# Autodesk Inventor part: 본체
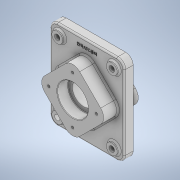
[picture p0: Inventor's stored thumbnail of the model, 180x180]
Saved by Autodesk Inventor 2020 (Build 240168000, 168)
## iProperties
Created: 2021-07
Part Number: 본체
Material: 일반
Document SubType Name: Modeling
Designer: Owner
Density: 1 g/cm^3
Appearance: 기본값
Mass: 807.977 g
Surface Area: 961.758 cm^2
Volume: 807.977 cm^3
Author: Owner
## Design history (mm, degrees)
sketch "스케치1"
  geometry: L1 (-75, -90)-(75, -90); L2 (75, -90)-(75, 90); L3 (75, 90)-(-75, 90); L4 (-75, 90)-(-75, -90); L5 (-75, -90)-(75, 90); L6 (75, -90)-(-75, 90); 1 further point
  constraints: 12 end point, 2 midpoint, 2 parallel, 1 horizontal, 1 perpendicular
  dimensions: "d0" = 150 distance of L3.end L2.end; "d1" = 180 distance of L2.end L1.end
extrude "돌출1" new body sketch "스케치1" stored distance "d2" = 18; taper "d3" = 0 deg
sketch "스케치2"
  geometry: L1 (-70.711, 0)-(0, 70.711); L2 (0, 70.711)-(70.711, 0); L3 (70.711, 0)-(0, -70.711); L4 (0, -70.711)-(-70.711, 0); L5 (-70.711, 0)-(70.711, 0); L6 (0, 70.711)-(0, -70.711); 2 further points
  constraints: 12 end point, 2 horizontal alignment, 2 midpoint, 2 parallel, 2 vertical alignment, 1 perpendicular
  dimensions: "d4" = 100 distance of L1.end L2.end; "d5" = 100 distance of L3.end L1.start (derived)
extrude "돌출2" join sketch "스케치2" distance "d6" = 29; taper "d7" = 0 deg
sketch "스케치3"
  geometry: L1 (-70.711, 0)-(0, 70.711); L2 (0, 70.711)-(70.711, 0); L3 (70.711, 0)-(0, -70.711); L4 (0, -70.711)-(-70.711, 0); L5 (-70.711, 0)-(70.711, 0); L6 (0, 70.711)-(0, -70.711); 2 further points
  constraints: 12 end point, 2 horizontal alignment, 2 midpoint, 2 parallel, 2 vertical alignment, 1 perpendicular
  dimensions: "d8" = 100 distance of L1.end L2.end; "d9" = 100 distance of L3.end L1.start (derived)
extrude "돌출3" join sketch "스케치3" distance "d10" = 23; taper "d11" = 0 deg
sketch "스케치5"
  geometry: C1 r 31 at (0, 0); 1 further point
  constraints: 1 centre point, 1 coincident
  dimensions: "d15" = 62 diameter of C1
extrude "돌출5" cut sketch "스케치5" distance "d16" = 22; taper "d17" = 0 deg
sketch "스케치6"
  geometry: C1 r 31 at (0, 0); 1 further point
  constraints: 1 centre point, 1 coincident
  dimensions: "d18" = 62 diameter of C1
extrude "돌출6" cut sketch "스케치6" distance "d19" = 22; taper "d20" = 0 deg
sketch "스케치7"
  geometry: C1 r 22.5 at (0, 0); 1 further point
  constraints: 1 centre point, 1 coincident
  dimensions: "d21" = 45 diameter of C1
extrude "돌출7" cut sketch "스케치7" extent not by distance; stored distance "d22" = 22; taper "d23" = 0 deg
sketch "스케치8"
  geometry: C1 r 31 at (0, 0) reference; 5 further points
  constraints: 2 horizontal alignment, 2 vertical alignment
  dimensions: "d24" = 48 distance of point (0, 0) point (0, 48); "d25" = 48 distance of point (0, -48) point (0, 0); "d26" = 48 distance of point (0, 0) point (48, 0); "d27" = 48 distance of point (0, 0) point (-48, 0)
hole "구멍1" sketch "스케치8" at (0, 48), (-48, 0), (48, 0), (0, -48) diameter "d28" = 4.917; stored, may be unused: countersink angle "d32" = 90 deg, drill point angle "d34" = 118 deg; dims "d29" = 10, "d30" = 4, "d31" = 2, "d33" = 13
fillet "모깎기1" dims "d42" = 15
fillet "모깎기2" dims "d52" = 20
chamfer "모따기1" distance "d53" = 1; stored, may be unused: second distance "d54" = 2, angle "d55" = 45 deg
fillet "모깎기3" dims "d56" = 1
fillet "모깎기4" dims "d57" = 3
fillet "모깎기5" dims "d58" = 3
fillet "모깎기6" dims "d59" = 3
sketch "스케치14"
  geometry: C1 r 11 at (-55, 70); C2 r 11 at (55, 70); C3 r 11 at (55, -70); C4 r 11 at (-55, -70); 1 further point
  constraints: 4 centre point
  dimensions: "d73" = 55 horizontal distance of point (0, 0) C2.centre; "d74" = 55 horizontal distance of C1.centre point (0, 0); "d75" = 55 horizontal distance of C4.centre point (0, 0); "d76" = 55 horizontal distance of C3.centre point (0, 0); "d77" = 70 vertical distance of point (0, 0) C2.centre; "d78" = 70 vertical distance of C3.centre point (0, 0); "d79" = 70 vertical distance of point (0, 0) C1.centre; "d80" = 70 vertical distance of C4.centre point (0, 0); "d81" = 22 diameter of C1; "d82" = 22 diameter of C2; "d83" = 22 diameter of C3; "d84" = 22 diameter of C4
extrude "돌출12" join sketch "스케치14" distance "d85" = 5; taper "d86" = 0 deg
sketch "스케치15"
  geometry: C1 r 11 at (0, 0) reference; C2 r 11 at (0, 0) reference; C3 r 5.5 at (0, 0); 1 further point
  constraints: 1 centre point, 1 coincident
  dimensions: "d87" = 11 diameter of C3
extrude "돌출13" cut sketch "스케치15" distance "d88" = 23; taper "d89" = 0 deg
fillet "모깎기7" dims "d90" = 3
sketch "스케치16"
  geometry: L1 (60, 90)-(-60, 90) reference; 2 further points
  constraints: 1 vertical alignment, 1 other
  dimensions: "d91" = 15 distance from line of point (0, 75) L1
feature "엠보싱1" sketch "스케치16" dims "d0" = 150, "d1" = 180, "d8" = 100, "d9" = 100 (derived), "d92" = 0.5, "d93" = 0
sketch "스케치17"
  geometry: 1 further point
sketch "스케치18"
  geometry: C1 r 22.5 at (0, 0) reference; C2 r 48 at (0, 0); C3 r 2.458 at (0, 48) reference; C4 r 2.458 at (-48, 0) reference; C5 r 2.458 at (0, -48) reference; C6 r 2.458 at (48, 0) reference; 5 further points
  constraints: 5 coincident, 1 centre point
  dimensions: "d94" = 96 diameter of C2
hole "구멍3" sketch "스케치18" at (0, 48), (48, 0), (0, -48), (-48, 0) diameter "d95" = 4.917; stored, may be unused: countersink angle "d99" = 90 deg, drill point angle "d101" = 118 deg; dims "d96" = 10, "d97" = 4, "d98" = 2, "d100" = 13
node "솔리드1"
mirror "미러5"
mirror "미러6"
feature "A9D066F2-1C7D-4E18-AEED-F7BC21143FA4" dims "d28" = 4.917, "d29" = 10, "d30" = 4, "d31" = 2, "d32" = 90 deg, "d33" = 13, "d34" = 118 deg
